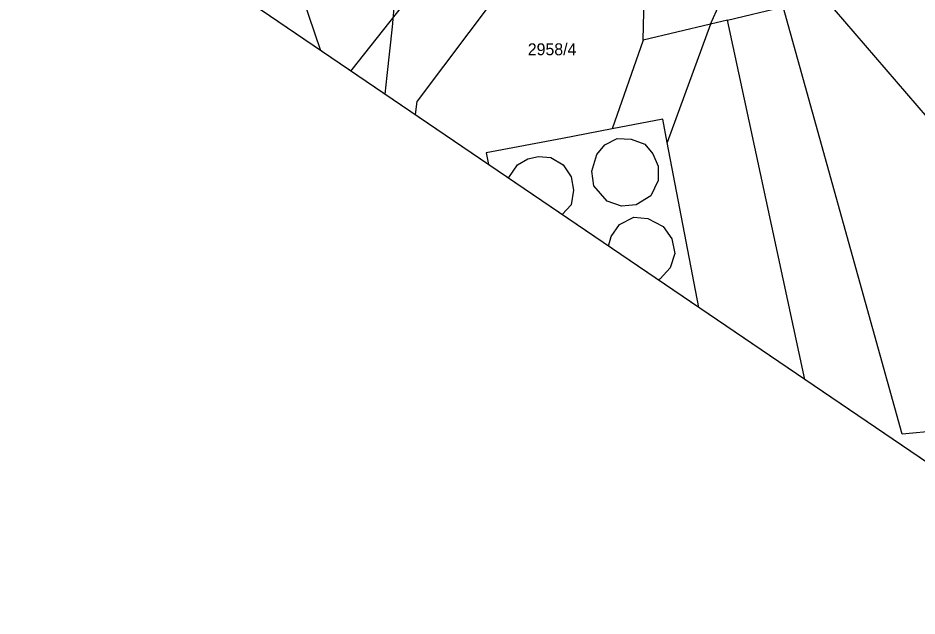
# Model space of a CAD drawing. Extents: x -621145 to -620023, y -1122866 to -1121971.
# Drawn here: x -620574.9 to -620461.4, y -1122701.2 to -1122625.8 of the extents above; entities that cross this region are included whole.
import ezdxf

# ---------------------------------------------------------------- set-up
doc = ezdxf.new("R2010")
doc.units = 0
for name, color, linetype in [('RÁMY', 7, 'Continuous'), ('VAS stoka', 7, 'Continuous'), ('Vrstva 55', 7, 'Continuous'), ('Vrstva 56', 7, 'Continuous'), ('Vrstva 57', 7, 'Continuous')]:
    doc.layers.add(name, color=color, linetype=linetype)

msp = doc.modelspace()

# ---------------------------------------------------------------- linework, layer by layer
at = {"layer": 'RÁMY'}
for points in [[(-621061.56, -1122093.92), (-620106.07, -1122742.82), (-620189.51, -1122865.67), (-621144.99, -1122216.77)], [(-620887.83, -1122211.9), (-620106.07, -1122742.82), (-620189.51, -1122865.67), (-620971.26, -1122334.75)]]:
    msp.add_lwpolyline(points, close=True, dxfattribs=at)
at = {"layer": 'VAS stoka'}
msp.add_lwpolyline([(-620528.56, -1122635.4), (-620528.28, -1122633.03), (-620527.95, -1122629.96), (-620527.63, -1122626.89), (-620527.31, -1122623.54), (-620526.99, -1122620.19), (-620526.62, -1122616.34), (-620526.25, -1122612.49), (-620526.12, -1122611.03), (-620525.99, -1122609.57), (-620526.07, -1122607.23), (-620526.16, -1122604.89), (-620526.43, -1122604.5), (-620526.7, -1122604.12), (-620528.73, -1122602.65), (-620530.75, -1122601.19), (-620532.84, -1122599.89), (-620534.92, -1122598.59), (-620537.95, -1122593.97), (-620540.97, -1122589.34), (-620542.16, -1122587.59), (-620543.34, -1122585.84), (-620543.8, -1122585.43), (-620544.25, -1122585.03)], dxfattribs=at)
at = {"layer": 'Vrstva 55'}
for p, q in [((-620562.8, -1122553.35), (-620536.71, -1122629.87)), ((-620532.9, -1122632.46), (-620510.44, -1122604.21)), ((-620503.19, -1122607.95), (-620524.52, -1122636.25)), ((-620495.96, -1122628.58), (-620495.65, -1122615.65)), ((-620434.88, -1122667.63), (-620473.14, -1122623.15)), ((-620485.31, -1122626.04), (-620478.32, -1122624.38)), ((-620463.28, -1122678.3), (-620478.32, -1122624.38)), ((-620487.46, -1122626.56), (-620495.96, -1122628.58)), ((-620485.31, -1122626.04), (-620487.46, -1122626.56)), ((-620475.57, -1122671.39), (-620485.31, -1122626.04)), ((-620524.73, -1122638.01), (-620524.52, -1122636.25)), ((-620493.5, -1122638.55), (-620499.9, -1122639.77)), ((-620492.94, -1122641.47), (-620493.5, -1122638.55)), ((-620499.9, -1122639.77), (-620506.17, -1122640.97)), ((-620506.17, -1122640.97), (-620515.78, -1122642.8)), ((-620488.95, -1122662.31), (-620492.94, -1122641.47)), ((-620515.78, -1122642.8), (-620515.5, -1122644.28)), ((-620451.85, -1122677.25), (-620463.28, -1122678.3))]:
    msp.add_line(p, q, dxfattribs=at)
at = {"layer": 'Vrstva 56'}
for p, q in [((-620487.46, -1122626.56), (-620480.79, -1122611.41)), ((-620487.46, -1122626.56), (-620492.94, -1122641.47)), ((-620495.96, -1122628.58), (-620499.9, -1122639.77)), ((-620500.81, -1122641.76), (-620499.26, -1122640.98)), ((-620499.26, -1122640.98), (-620497.47, -1122641.06)), ((-620497.47, -1122641.06), (-620495.76, -1122641.68)), ((-620501.82, -1122643), (-620500.81, -1122641.76)), ((-620495.76, -1122641.68), (-620494.75, -1122642.92)), ((-620511.84, -1122644.32), (-620510.52, -1122643.55)), ((-620510.52, -1122643.55), (-620509.2, -1122643.23)), ((-620509.2, -1122643.23), (-620507.65, -1122643.39)), ((-620507.65, -1122643.39), (-620506.09, -1122644.32)), ((-620502.44, -1122645.1), (-620501.82, -1122643)), ((-620494.75, -1122642.92), (-620494.06, -1122644.48)), ((-620512.93, -1122645.88), (-620511.84, -1122644.32)), ((-620506.09, -1122644.32), (-620505.08, -1122645.8)), ((-620494.06, -1122644.48), (-620494.06, -1122646.26)), ((-620512.93, -1122646.02), (-620512.93, -1122645.88)), ((-620505.08, -1122645.8), (-620504.77, -1122647.51)), ((-620502.21, -1122646.96), (-620502.44, -1122645.1)), ((-620500.5, -1122648.9), (-620502.21, -1122646.96)), ((-620494.06, -1122646.26), (-620494.99, -1122648.21)), ((-620504.77, -1122647.51), (-620505.08, -1122649.37)), ((-620498.71, -1122649.52), (-620500.5, -1122648.9)), ((-620494.99, -1122648.21), (-620496.85, -1122649.37)), ((-620505.08, -1122649.37), (-620506.22, -1122650.58)), ((-620496.85, -1122649.37), (-620498.71, -1122649.52)), ((-620498.95, -1122651.85), (-620497.16, -1122650.92)), ((-620497.16, -1122650.92), (-620495.38, -1122651.08)), ((-620495.38, -1122651.08), (-620493.43, -1122652.09)), ((-620500.03, -1122653.33), (-620498.95, -1122651.85)), ((-620493.43, -1122652.09), (-620492.35, -1122653.64)), ((-620500.34, -1122654.57), (-620500.03, -1122653.33)), ((-620492.35, -1122653.64), (-620491.96, -1122655.5)), ((-620491.96, -1122655.5), (-620492.58, -1122657.29)), ((-620492.58, -1122657.29), (-620493.82, -1122658.69)), ((-620493.82, -1122658.69), (-620494.1, -1122658.81))]:
    msp.add_line(p, q, dxfattribs=at)

# ---------------------------------------------------------------- texts
at = {"layer": 'Vrstva 57'}
msp.add_text('2958/4', height=1.5, dxfattribs=at).set_placement((-620510.54, -1122630.47))

doc.saveas('drawing.dxf')
